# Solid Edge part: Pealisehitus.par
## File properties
Author: Olev
Template: Normal.par
Last saved by: haldur
Revision: 51
Application: Solid Edge
Accuracy: 0,990
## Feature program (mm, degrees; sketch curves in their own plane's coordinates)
sketch for "unnamed Protrusion 1" plane through (0, 0, 0) normal (0, 0, 1) x-axis (1, 0, 0)
  line (0, 32) -> (235, 32)
  line (235, 32) -> (235, 0)
  line (235, -32) -> (235, 0)
  line (0, -32) -> (235, -32)
  line (0, -32) -> (-235, -32)
  line (-235, -32) -> (-235, 0)
  line (-235, 32) -> (-235, 0)
  line (0, 32) -> (-235, 32)
extrude "unnamed Protrusion 1" add finite 75 along +normal
sketch for "ExtrudedCutout_1" plane through (-260.1685, 0, 102.7993) normal (0.741314, 0, 0.671159) x-axis (0, 1, 0)
  bspline degree 3 poles (-32, -100.5693) (-25.8183, -95.5068) (-15.1516, -93.0166) (0, -93.0985) knots 0 1 multiplicities 4 4
  bspline degree 3 poles (32, -100.5693) (25.8183, -95.5068) (15.1516, -93.0166) (0, -93.0985) knots 0 1 multiplicities 4 4
  line (32, -100.5693) -> (39.2571, -100.5693)
  line (39.2571, -100.5693) -> (39.2571, -25.2816)
  line (-39.2571, -25.2816) -> (39.2571, -25.2816)
  line (-39.2571, -100.5693) -> (-39.2571, -25.2816)
  line (-32, -100.5693) -> (-39.2571, -100.5693)
extrude "ExtrudedCutout_1" cut finite 178.1207 symmetric
sketch for "ExtrudedCutout_2" plane through (40.0277, 0, 75) normal (0, 0, 1) x-axis (1, 0, 0)
  line (185.7988, 32) -> (185.7988, -32)
  line (185.7988, -32) -> (185.7988, -40.3114)
  line (185.7988, -40.3114) -> (207.4022, -40.3114)
  line (207.4022, -40.3114) -> (207.4022, 39.335)
  line (207.4022, 39.335) -> (185.7988, 39.335)
  line (185.7988, 39.335) -> (185.7988, 32)
extrude "ExtrudedCutout_2" cut finite 93.4921 along -normal
sketch for "ExtrudedCutout_3" plane through (0.9788, -32, 37.5) normal (0, -1, 0) x-axis (1, 0, 0)
  line (224.8477, -37.5) -> (224.8477, -25.5)
  line (224.8477, -25.5) -> (216.8477, -25.5)
  line (216.8477, -25.5) -> (216.8477, -13.5)
  line (216.8477, -13.5) -> (208.8477, -13.5)
  line (208.8477, -13.5) -> (208.8477, -1.5)
  line (208.8477, -1.5) -> (200.8477, -1.5)
  line (200.8477, -1.5) -> (200.8477, 10.5)
  line (200.8477, 10.5) -> (190.8477, 10.5)
  line (190.8477, 10.5) -> (190.8477, 22.5)
  line (190.8477, 22.5) -> (190.8477, 41.104)
  line (190.8477, 41.104) -> (235.8886, 41.104)
  line (235.8886, 41.104) -> (235.8886, -37.5)
  line (235.8886, -37.5) -> (224.8477, -37.5)
extrude "ExtrudedCutout_3" cut finite 99.1318 along -normal
sketch for "ExtrudedCutout_4" plane through (0.9788, -32, 37.5) normal (0, -1, 0) x-axis (1, 0, 0)
  line (190.8477, 22.5) -> (-84.5346, 22.5)
  line (-84.5346, 22.5) -> (-84.5346, 50.8209)
  line (-84.5346, 50.8209) -> (201.9237, 50.8209)
  line (201.9237, 50.8209) -> (201.9237, 22.5)
  line (201.9237, 22.5) -> (190.8477, 22.5)
extrude "ExtrudedCutout_4" cut finite 85.7158 along -normal
sketch for "ExtrudedProtrusion_2" plane through (54.1353, 0, 60) normal (0, 0, 1) x-axis (1, 0, 0)
  line (-1.754, 0) -> (-1.754, 21.0355)
  line (-1.754, 21.0355) -> (82.1348, 21.0355)
  line (82.1348, 21.0355) -> (82.1348, 0)
  line (82.1348, -21.0355) -> (82.1348, 0)
  line (-1.754, -21.0355) -> (82.1348, -21.0355)
  line (-1.754, 0) -> (-1.754, -21.0355)
extrude "ExtrudedProtrusion_2" add finite 64.8527 along +normal
sketch for "ExtrudedCutout_5" plane through (94.3257, -21.0355, 92.4263) normal (0, -1, 0) x-axis (1, 0, 0)
  line (-41.9444, -32.4263) -> (-7.3597, 32.4263)
  line (-7.3597, 32.4263) -> (-4.3956, 35.5146)
  line (-4.3956, 35.5146) -> (43.1232, 35.5146)
  line (43.1232, 35.5146) -> (41.9444, 32.4263)
  line (22.306, -2.8036) -> (41.9444, 32.4263)
  line (41.9444, -32.4263) -> (22.306, -2.8036)
  line (41.9444, -32.4263) -> (46.6933, -30.5932)
  line (46.6933, -30.5932) -> (50.8789, 37.9767)
  line (50.8789, 37.9767) -> (-47.2364, 37.9767)
  line (-47.2364, 37.9767) -> (-46.4978, -27.7617)
  line (-46.4978, -27.7617) -> (-41.9444, -32.4263)
extrude "ExtrudedCutout_5" cut finite 54.9152 along -normal
sketch for "unnamed Cutout 1" plane through (0, 0, 0) normal (1, 0, 0) x-axis (0, 1, 0)
  line (-10.3557, 124.8527) -> (0, 124.8527)
  line (-21.0355, 60) -> (-10.3557, 124.8527)
  line (-21.0355, 60) -> (-25.1495, 61.8566)
  line (-25.1495, 61.8566) -> (-25.1495, 129.9082)
  line (-25.1495, 129.9082) -> (0, 129.9082)
  line (25.1495, 129.9082) -> (0, 129.9082)
  line (25.1495, 61.8566) -> (25.1495, 129.9082)
  line (21.0355, 60) -> (25.1495, 61.8566)
  line (21.0355, 60) -> (10.3557, 124.8527)
  line (10.3557, 124.8527) -> (0, 124.8527)
extrude "unnamed Cutout 1" cut finite 157.4428 along +normal
sketch for "unnamed Cutout 2" plane through (0.9788, -32, 37.5) normal (0, -1, 0) x-axis (1, 0, 0)
  line (82.6021, 81.0048) -> (135.2913, 87.3527)
  line (135.2913, 87.3527) -> (140.7067, 92.3603)
  line (140.7067, 92.3603) -> (77.6808, 92.3603)
  line (77.6808, 92.3603) -> (82.6021, 81.0048)
extrude "unnamed Cutout 2" cut finite 67.2706 along -normal
sketch for "ExtrudedProtrusion_3" plane through (94.3257, -15.6956, 92.4263) normal (0, -0.98671, 0.16249) x-axis (1, 0, 0)
  line (37.8211, 23.7794) -> (22.4354, 23.7794)
  line (22.4354, 23.7794) -> (15.0569, 11.0198)
  line (6.5938, 23.9063) -> (15.0569, 11.0198)
  line (6.5938, 23.9063) -> (-9.1147, 23.9063)
  line (-9.1147, 23.9063) -> (7.6257, -1.831)
  line (7.6257, -1.831) -> (-7.7779, -28.4682)
  line (9.1866, -28.5218) -> (-7.7779, -28.4682)
  line (16.4076, -15.3327) -> (9.1866, -28.5218)
  line (16.4076, -15.3327) -> (25.0066, -28.5532)
  line (25.0066, -28.5532) -> (41.0463, -28.5532)
  line (23.6619, -2.0826) -> (41.0463, -28.5532)
  line (37.8211, 23.7794) -> (23.6619, -2.0826)
extrude "ExtrudedProtrusion_3" add finite 3.2873 along +normal
sketch for "ExtrudedProtrusion_4" plane through (126.3039, 15.6277, 92.8383) normal (0, 0.98671, 0.16249) x-axis (-1, 0, 0)
  line (41.1343, 23.63) -> (26.1198, 23.63)
  line (26.1198, 23.63) -> (16.6608, 9.0922)
  line (16.6608, 9.0922) -> (8.7593, 23.3825)
  line (8.7593, 23.3825) -> (-6.2195, 23.3825)
  line (-6.2195, 23.3825) -> (8.5574, -3.3621)
  line (8.5574, -3.3621) -> (-7.7779, -28.4682)
  line (7.1705, -28.5218) -> (-7.7779, -28.4682)
  line (15.4415, -15.8215) -> (7.1705, -28.5218)
  line (15.4415, -15.8215) -> (22.4586, -28.5218)
  line (22.4586, -28.5218) -> (37.4586, -28.5218)
  line (37.4586, -28.5218) -> (23.5511, -3.3692)
  line (41.1343, 23.63) -> (23.5511, -3.3692)
extrude "ExtrudedProtrusion_4" add finite 3.2873 along +normal
sketch for "ExtrudedCutout_8" plane through (110.2915, -19.3167, 90.6679) normal (0, -0.98671, 0.16249) x-axis (1, 0, 0)
  line (-22.8152, 24.926) -> (-9.9704, 24.926)
  line (-9.9704, 24.926) -> (-0.9329, 10.9679)
  line (-0.9329, 10.9679) -> (7.0961, 24.8362)
  line (7.0961, 24.8362) -> (19.7612, 24.8362)
  line (19.7612, 24.8362) -> (6.1333, 0.0542)
  line (6.1333, 0.0542) -> (22.3909, -25.055)
  line (22.3909, -25.055) -> (9.0408, -25.055)
  line (9.0408, -25.055) -> (0.0676, -10.9763)
  line (0.0676, -10.9763) -> (-7.4554, -24.6566)
  line (-7.4554, -24.6566) -> (-21.5577, -24.6566)
  line (-21.5577, -24.6566) -> (-7.1141, 0.2915)
  line (-7.1141, 0.2915) -> (-22.8152, 24.926)
extrude "ExtrudedCutout_8" cut finite 2 along -normal
sketch for "ExtrudedCutout_9" plane through (109.6697, 19.2592, 91.0173) normal (0, 0.98671, 0.16249) x-axis (-1, 0, 0)
  line (-21.1282, 24.7043) -> (-8.353, 24.7043)
  line (-8.353, 24.7043) -> (-0.041, 9.6534)
  line (-0.041, 9.6534) -> (9.8973, 24.9149)
  line (9.8973, 24.9149) -> (22.6023, 24.9149)
  line (22.6023, 24.9149) -> (5.7726, -0.8736)
  line (5.7726, -0.8736) -> (19.0926, -24.9926)
  line (19.0926, -24.9926) -> (6.3876, -24.9926)
  line (6.3876, -24.9926) -> (-1.1193, -11.4342)
  line (-1.1193, -11.4342) -> (-9.9675, -24.9926)
  line (-9.9675, -24.9926) -> (-22.6023, -24.9926)
  line (-22.6023, -24.9926) -> (-6.9341, -0.932)
  line (-6.9341, -0.932) -> (-21.1282, 24.7043)
extrude "ExtrudedCutout_9" cut finite 2 along -normal
sketch for "ExtrudedCutout_10" plane through (0.9788, -32, 37.5) normal (0, -1, 0) x-axis (1, 0, 0)
  line (-158.576, 22.5) -> (-177.5755, 22.5)
  line (-189.0786, 10.5) -> (-177.5755, 22.5)
  line (-158.576, 10.5) -> (-189.0786, 10.5)
  line (-158.576, 22.5) -> (-158.576, 10.5)
extrude "ExtrudedCutout_10" cut finite 77.5623 along -normal
lofted protrusion "unnamed LoftedProtrusion 1"
sketch for "unnamed Cutout 3" #1 plane through (-157.5972, -35.2209, 54) normal (1, 0, 0) x-axis (0, 1, 0)
  line (-3.2208, 6) -> (0, -6)
  line (0, -6) -> (0, -8.7195)
  line (0, -8.7195) -> (-5.6987, -8.7195)
  line (-5.6987, -8.7195) -> (-5.6987, 6)
  line (-5.6987, 6) -> (-3.2208, 6)
sketch for "unnamed Cutout 3" #2 plane through (-157.5972, -35.2209, 54) normal (1, 0, 0) x-axis (0, 1, 0)
  line (73.6625, 6) -> (70.4417, -6)
  line (70.4417, -6) -> (70.4417, -8.7195)
  line (70.4417, -8.7195) -> (76.1404, -8.7195)
  line (76.1404, -8.7195) -> (76.1404, 6)
  line (76.1404, 6) -> (73.6625, 6)
extrude "unnamed Cutout 3" cut finite 35.2484 along -normal
fillet "Round_1" radius 3
fillet "Round_3" radius 1.5
sketch for "ExtrudedCutout_14" #1 plane through (71.2567, -32, -18.3838) normal (0, -1, 0) x-axis (-1, 0, 0)
sketch for "ExtrudedCutout_14" #2 plane through (71.2567, -32, -18.3838) normal (0, -1, 0) x-axis (-1, 0, 0)
  line (-139.945, -20.1644) -> (-139.945, -28.4187)
  line (-139.945, -28.4187) -> (-131.9686, -28.4187)
  line (-131.9686, -20.1644) -> (-131.9686, -28.4187)
  line (-131.9686, -20.1644) -> (-139.945, -20.1644)
extrude "ExtrudedCutout_14" cut finite 0.1 along -normal
extrude "unnamed Cutout 4" cut finite 0.1
extrude "unnamed Cutout 5" cut finite 0.1
extrude "unnamed Cutout 6" cut finite 0.1
extrude "unnamed Cutout 7" cut finite 0.1
extrude "unnamed Cutout 8" cut finite 0.1
extrude "unnamed Cutout 9" cut finite 0.1
extrude "unnamed Cutout 10" cut finite 0.1
extrude "unnamed Cutout 11" cut finite 0.1
extrude "unnamed Cutout 12" cut finite 0.1
extrude "unnamed Cutout 13" cut finite 0.1
extrude "unnamed Cutout 14" cut finite 0.1
extrude "unnamed Cutout 15" cut finite 0.1
extrude "unnamed Cutout 16" cut finite 0.1
extrude "unnamed Cutout 17" cut finite 0.1
extrude "unnamed Cutout 18" cut finite 0.1
extrude "unnamed Cutout 19" cut finite 0.1
extrude "unnamed Cutout 20" cut finite 0.1
extrude "unnamed Cutout 21" cut finite 0.1
extrude "unnamed Cutout 22" cut finite 0.1
extrude "unnamed Cutout 23" cut finite 0.1
extrude "unnamed Cutout 24" cut finite 0.1
extrude "unnamed Cutout 25" cut finite 0.1
extrude "unnamed Cutout 26" cut finite 0.1
extrude "unnamed Cutout 27" cut finite 0.1
extrude "unnamed Cutout 28" cut finite 0.1
extrude "unnamed Cutout 29" cut finite 0.1
extrude "unnamed Cutout 30" cut finite 0.1
extrude "unnamed Cutout 31" cut finite 0.1
extrude "unnamed Cutout 32" cut finite 0.1
extrude "unnamed Cutout 33" cut finite 0.1
extrude "unnamed Cutout 34" cut finite 0.1
extrude "unnamed Cutout 35" cut finite 0.1
extrude "unnamed Cutout 36" cut finite 0.1
extrude "unnamed Cutout 37" cut finite 0.1
extrude "unnamed Cutout 38" cut finite 0.1
extrude "unnamed Cutout 39" cut finite 0.1
extrude "unnamed Cutout 40" cut finite 0.1
extrude "unnamed Cutout 41" cut finite 0.1
extrude "unnamed Cutout 42" cut finite 0.1
extrude "unnamed Cutout 43" cut finite 0.1
extrude "unnamed Cutout 44" cut finite 0.1
extrude "unnamed Cutout 45" cut finite 0.1
extrude "unnamed Cutout 46" cut finite 0.1
extrude "unnamed Cutout 47" cut finite 0.1
extrude "unnamed Cutout 48" cut finite 0.1
extrude "unnamed Cutout 49" cut finite 0.1
extrude "unnamed Cutout 50" cut finite 0.1
extrude "unnamed Cutout 51" cut finite 0.1
extrude "unnamed Cutout 52" cut finite 0.1
extrude "unnamed Cutout 53" cut finite 0.1
extrude "unnamed Cutout 54" cut finite 0.1
extrude "unnamed Cutout 55" cut finite 0.1
extrude "unnamed Cutout 56" cut finite 0.1
extrude "unnamed Cutout 57" cut finite 0.1
extrude "unnamed Cutout 58" cut finite 0.1
extrude "unnamed Cutout 59" cut finite 0.1
extrude "unnamed Cutout 60" cut finite 0.1
extrude "unnamed Cutout 61" cut finite 0.1
extrude "unnamed Cutout 62" cut finite 0.1
extrude "unnamed Cutout 63" cut finite 0.1
extrude "unnamed Cutout 64" cut finite 0.1
extrude "unnamed Cutout 65" cut finite 0.1
extrude "unnamed Cutout 66" cut finite 0.1
extrude "unnamed Cutout 67" cut finite 0.1
extrude "unnamed Cutout 68" cut finite 0.1
extrude "unnamed Cutout 69" cut finite 0.1
extrude "unnamed Cutout 70" cut finite 0.1
extrude "unnamed Cutout 71" cut finite 0.1
extrude "unnamed Cutout 72" cut finite 0.1
extrude "unnamed Cutout 73" cut finite 0.1
extrude "unnamed Cutout 74" cut finite 0.1
sketch for "unnamed Cutout 75" #1 plane through (71.3444, 32, 29.8927) normal (0, 1, 0) x-axis (-1, 0, 0)
  line (-139.945, -20.1644) -> (-139.945, -28.4187)
  line (-139.945, -28.4187) -> (-131.9686, -28.4187)
  line (-131.9686, -20.1644) -> (-131.9686, -28.4187)
  line (-131.9686, -20.1644) -> (-139.945, -20.1644)
sketch for "unnamed Cutout 75" #2 plane through (71.3444, 32, 29.8927) normal (0, 1, 0) x-axis (-1, 0, 0)
  line (-131.4462, -28.4187) -> (-123.5499, -28.4187)
  line (-123.5499, -28.4187) -> (-123.5499, -20.1644)
  line (-123.5499, -20.1644) -> (-131.4462, -20.1644)
  line (-131.4462, -20.1644) -> (-131.4462, -28.4187)
extrude "unnamed Cutout 75" cut finite 0.1 along -normal
extrude "unnamed Cutout 76" cut finite 0.1
extrude "unnamed Cutout 77" cut finite 0.1
extrude "unnamed Cutout 78" cut finite 0.1
extrude "unnamed Cutout 79" cut finite 0.1
extrude "unnamed Cutout 80" cut finite 0.1
extrude "unnamed Cutout 81" cut finite 0.1
extrude "unnamed Cutout 82" cut finite 0.1
extrude "unnamed Cutout 83" cut finite 0.1
extrude "unnamed Cutout 84" cut finite 0.1
extrude "unnamed Cutout 85" cut finite 0.1
extrude "unnamed Cutout 86" cut finite 0.1
extrude "unnamed Cutout 87" cut finite 0.1
extrude "unnamed Cutout 88" cut finite 0.1
extrude "unnamed Cutout 89" cut finite 0.1
extrude "unnamed Cutout 90" cut finite 0.1
extrude "unnamed Cutout 91" cut finite 0.1
extrude "unnamed Cutout 92" cut finite 0.1
extrude "unnamed Cutout 93" cut finite 0.1
extrude "unnamed Cutout 94" cut finite 0.1
extrude "unnamed Cutout 95" cut finite 0.1
extrude "unnamed Cutout 96" cut finite 0.1
extrude "unnamed Cutout 97" cut finite 0.1
extrude "unnamed Cutout 98" cut finite 0.1
extrude "unnamed Cutout 99" cut finite 0.1
extrude "unnamed Cutout 100" cut finite 0.1
extrude "unnamed Cutout 101" cut finite 0.1
extrude "unnamed Cutout 102" cut finite 0.1
extrude "unnamed Cutout 103" cut finite 0.1
extrude "unnamed Cutout 104" cut finite 0.1
extrude "unnamed Cutout 105" cut finite 0.1
extrude "unnamed Cutout 106" cut finite 0.1
extrude "unnamed Cutout 107" cut finite 0.1
extrude "unnamed Cutout 108" cut finite 0.1
extrude "unnamed Cutout 109" cut finite 0.1
extrude "unnamed Cutout 110" cut finite 0.1
extrude "unnamed Cutout 111" cut finite 0.1
extrude "unnamed Cutout 112" cut finite 0.1
extrude "unnamed Cutout 113" cut finite 0.1
extrude "unnamed Cutout 114" cut finite 0.1
extrude "unnamed Cutout 115" cut finite 0.1
extrude "unnamed Cutout 116" cut finite 0.1
extrude "unnamed Cutout 117" cut finite 0.1
extrude "unnamed Cutout 118" cut finite 0.1
extrude "unnamed Cutout 119" cut finite 0.1
extrude "unnamed Cutout 120" cut finite 0.1
extrude "unnamed Cutout 121" cut finite 0.1
extrude "unnamed Cutout 122" cut finite 0.1
extrude "unnamed Cutout 123" cut finite 0.1
extrude "unnamed Cutout 124" cut finite 0.1
extrude "unnamed Cutout 125" cut finite 0.1
extrude "unnamed Cutout 126" cut finite 0.1
extrude "unnamed Cutout 127" cut finite 0.1
extrude "unnamed Cutout 128" cut finite 0.1
extrude "unnamed Cutout 129" cut finite 0.1
extrude "unnamed Cutout 130" cut finite 0.1
extrude "unnamed Cutout 131" cut finite 0.1
extrude "unnamed Cutout 132" cut finite 0.1
extrude "unnamed Cutout 133" cut finite 0.1
extrude "unnamed Cutout 134" cut finite 0.1
extrude "unnamed Cutout 135" cut finite 0.1
extrude "unnamed Cutout 136" cut finite 0.1
extrude "unnamed Cutout 137" cut finite 0.1
extrude "unnamed Cutout 138" cut finite 0.1
extrude "unnamed Cutout 139" cut finite 0.1
extrude "unnamed Cutout 140" cut finite 0.1
extrude "unnamed Cutout 141" cut finite 0.1
extrude "unnamed Cutout 142" cut finite 0.1
extrude "unnamed Cutout 143" cut finite 0.1
extrude "unnamed Cutout 144" cut finite 0.1
extrude "unnamed Cutout 145" cut finite 0.1
extrude "unnamed Cutout 146" cut finite 0.1
fillet "Round_4" radius 3
sketch for "ExtrudedProtrusion_6" #1 plane through (1.3396, -32, 37.5) normal (0, -1, 0) x-axis (1, 0, 0)
extrude "ExtrudedProtrusion_6" add finite 0.1 along +normal
sketch for "ExtrudedProtrusion_7" #1 plane through (1.3396, 32, 37.5) normal (0, 1, 0) x-axis (-1, 0, 0)
extrude "ExtrudedProtrusion_7" add finite 0.1 along +normal
sketch for "ExtrudedCutout_322" plane through (54.1353, 0, 60) normal (0, 0, 1) x-axis (1, 0, 0)
  arc centre (-38.512, 0) radius 21.5818 from (-16.9303, 0) to (-16.9303, 0) cw
extrude "ExtrudedCutout_322" cut finite 3 along -normal
fillet "Round_5" radius 1
sketch for "ExtrudedProtrusion_8" plane through (-119.2503, 0, 75) normal (0, 0, 1) x-axis (1, 0, 0)
  line (35.1795, -31.3835) -> (-19.4478, -31.3835)
  line (35.1795, 31.5383) -> (35.1795, -31.3835)
  line (35.1795, 31.5383) -> (-19.4478, 31.5383)
  bspline degree 3 poles (-19.4478, 31.5383) (-20.2314, 31.348) (-21.9999, 30.8916) (-24.6075, 28.5404) (-26.9839, 24.6994) (-29.4094, 20.2201) (-31.0684, 14.5848) (-32.0179, 8.8699) (-32.3054, 3.2224) (-32.2929, -1.5572) (-32.1385, -6.2936) (-31.4885, -10.9851) (-30.6787, -16.1111) (-29.1243, -20.7553) (-26.9175, -24.9819) (-24.7695, -28.3361) (-22.5449, -30.3422) (-20.7554, -31.1499) (-19.8815, -31.3102) (-19.4478, -31.3835) knots 0 0.0305 0.0801 0.1378 0.2199 0.2905 0.3813 0.4604 0.5255 0.5802 0.6575 0.7225 0.796 0.8599 0.9209 0.9605 0.9834 1 multiplicities 4 1 1 1 1 1 1 1 1 1 1 1 1 1 1 1 1 4
extrude "ExtrudedProtrusion_8" add finite 4 along +normal
sketch for "unnamed Cutout 147" plane through (-117.8132, 0.0774, 79) normal (0, 0, 1) x-axis (1, 0, 0)
  line (33.1924, 30.8441) -> (-20.8484, 30.8441)
  line (33.1924, -30.9048) -> (-20.8484, -30.9048)
  line (33.1924, 30.8441) -> (33.1924, -30.9048)
extrude "unnamed Cutout 147" cut finite 4 along -normal
sketch for "unnamed Cutout 148" plane through (-111.3844, -31.3835, 77) normal (0, -1, 0) x-axis (1, 0, 0)
  line (-27.051, 1.7303) -> (-27.051, -1.7303)
  line (-27.051, -1.7303) -> (26.9666, -1.7303)
  line (26.9666, -1.7303) -> (26.9666, 1.7303)
  line (26.9666, 1.7303) -> (-27.051, 1.7303)
extrude "unnamed Cutout 148" cut finite 0.1 along -normal
sketch for "unnamed Cutout 149" plane through (-111.3552, 31.5383, 76.9842) normal (0, 1, 0) x-axis (-1, 0, 0)
  line (-27.051, 1.7303) -> (-27.051, -1.7303)
  line (-27.051, -1.7303) -> (26.9666, -1.7303)
  line (26.9666, -1.7303) -> (26.9666, 1.7303)
  line (26.9666, 1.7303) -> (-27.051, 1.7303)
extrude "unnamed Cutout 149" cut finite 0.1 along -normal
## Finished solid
Body 1: solid body, 1771 faces, 4307 edges, 2857 vertices.
  Faces by surface: plane 1727, swept 27, cylinder 14, spline 2, blend 1
  Edges by curve: line 3905, spline 353, circle 20, ellipse 11, intersection 10, curve on surface 8
Bounding box of the edges (mm; curved faces can reach further): 460.827 x 76.883 x 124.853, from (-235, -38.4416, 0) to (225.8265, 38.4416, 124.8527).
Cylindrical faces by radius (mm): R1.5 x10, R3 x4
Planar faces by outward normal: +x 329, +y 164, +z 332, -x 321, -y 164, -z 331, oblique 86
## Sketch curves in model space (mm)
line (-171.0542, -38.5176, 60) -> (-157.5972, -38.4416, 60)
line (-157.5972, -38.4416, 60) -> (-157.5972, 0, 60)
line (-157.5972, 38.4416, 60) -> (-157.5972, 0, 60)
line (-171.0542, 38.5176, 60) -> (-157.5972, 38.4416, 60)
spline (-187.692, 0, 60) -> (-185.4871, 20.303, 60) -> (-171.0542, 38.5176, 60)
spline (-187.692, 0, 60) -> (-185.4871, -20.303, 60) -> (-171.0542, -38.5176, 60)
line (-157.5972, -38.4416, 48) -> (-162.9221, -38.4416, 48)
line (-157.5972, 0, 48) -> (-157.5972, -38.4416, 48)
line (-157.5972, 0, 48) -> (-157.5972, 38.4416, 48)
line (-157.5972, 38.4416, 48) -> (-162.9221, 38.4416, 48)
spline (-181.9827, 0, 48) -> (-178.1412, 22.258, 48) -> (-162.9221, 38.4416, 48)
spline (-181.9827, 0, 48) -> (-178.1412, -22.258, 48) -> (-162.9221, -38.4416, 48)
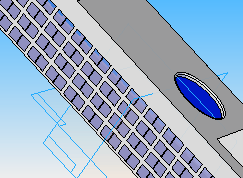
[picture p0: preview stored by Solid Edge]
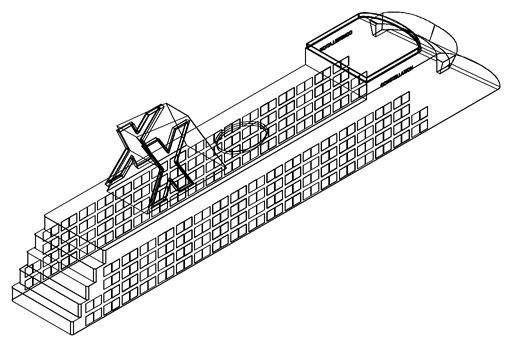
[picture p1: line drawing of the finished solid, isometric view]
